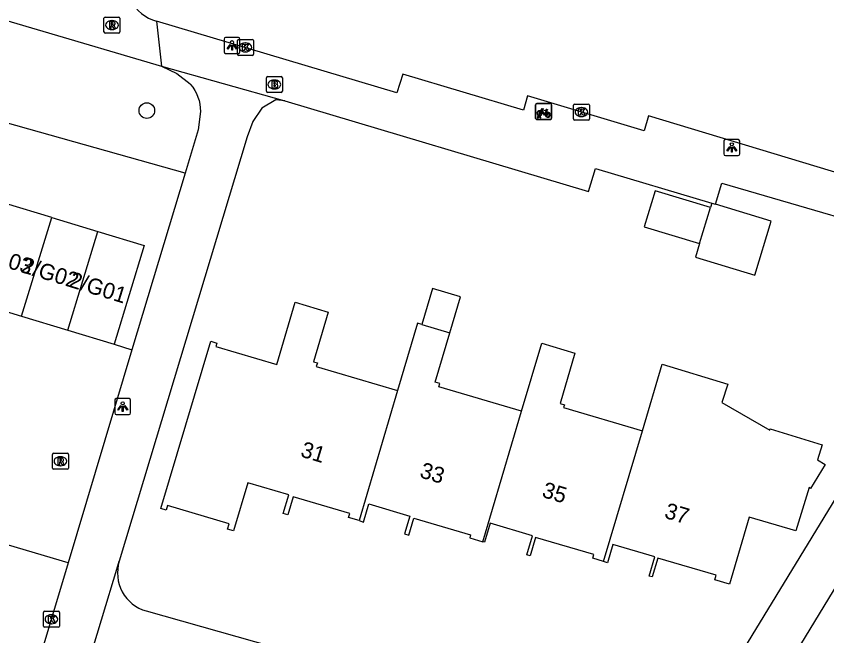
# Model space of a CAD drawing. Extents: x 162186 to 163152, y 385513 to 386513.
# Drawn here: x 162775.6 to 162826.3, y 386020.5 to 386059.3 of the extents above; entities that cross this region are included whole.
import ezdxf

# ---------------------------------------------------------------- set-up
doc = ezdxf.new("R2010")
doc.units = 0
for name, color, linetype in [('IMGEO_Boom', 7, 'Continuous'), ('IMGEO_Brandkraan', 7, 'Continuous'), ('IMGEO_Fietsenrek', 7, 'Continuous'), ('IMGEO_Groenvoorziening', 7, 'Continuous'), ('IMGEO_Kolk', 7, 'Continuous'), ('IMGEO_Lichtpunt', 7, 'Continuous'), ('IMGEO_Pand', 7, 'Continuous'), ('IMGEO_Pand_nummerreeks', 7, 'Continuous'), ('IMGEO_Rijbaan_lokaal_open', 7, 'Continuous'), ('IMGEO_Rioolput', 7, 'Continuous'), ('IMGEO_Voetpad_open', 7, 'Continuous')]:
    doc.layers.add(name, color=color, linetype=linetype)

msp = doc.modelspace()

# ---------------------------------------------------------------- linework, layer by layer
at = {"layer": 'IMGEO_Boom'}
msp.add_circle((162783.74, 386053.4), 0.489, dxfattribs=at)
at = {"layer": 'IMGEO_Brandkraan'}
for p, q in [((162791.228, 386054.612), (162791.228, 386055.464)), ((162791.303, 386055.538), (162792.155, 386055.538)), ((162792.229, 386055.464), (162792.229, 386054.612)), ((162791.716, 386055.318), (162791.741, 386055.318)), ((162792.155, 386054.538), (162791.303, 386054.538)), ((162791.739, 386054.758), (162791.714, 386054.758))]:
    msp.add_line(p, q, dxfattribs=at)
for points in [[(162791.228, 386054.612), (162791.228, 386055.464)], [(162791.303, 386055.538), (162792.155, 386055.538)], [(162792.229, 386055.464), (162792.229, 386054.612)], [(162791.576, 386055.238), (162791.576, 386054.838), (162791.789, 386054.838)], [(162791.807, 386055.238), (162791.576, 386055.238)], [(162791.755, 386055.157), (162791.701, 386055.157), (162791.701, 386055.081)], [(162791.701, 386055.081), (162791.754, 386055.081)], [(162791.763, 386055.005), (162791.701, 386055.005), (162791.701, 386054.924)], [(162791.701, 386054.924), (162791.763, 386054.924)], [(162792.155, 386054.538), (162791.303, 386054.538)]]:
    msp.add_lwpolyline(points, dxfattribs=at)
for centre, radius, start, end in [((162791.305, 386055.462), 0.0765, 91.552, 178.448), ((162791.305, 386055.462), 0.0765, 91.552, 178.448), ((162792.153, 386055.462), 0.0765, 1.552, 88.448), ((162792.153, 386055.462), 0.0765, 1.552, 88.448), ((162791.756, 386055.119), 0.0379, 267.8285, 90.9355), ((162791.764, 386054.964), 0.0404, 269.8759, 90.5077), ((162791.811, 386055.093), 0.145, 59.4692, 91.5367), ((162791.836, 386055.14), 0.0922, 285.5137, 58.1501), ((162791.841, 386054.948), 0.105, 301.3115, 78.989), ((162791.305, 386054.614), 0.0765, 181.552, 268.448), ((162791.305, 386054.614), 0.0765, 181.552, 268.448), ((162791.795, 386055.089), 0.251, 268.6676, 293.5347), ((162792.153, 386054.614), 0.0765, 271.552, 358.448), ((162792.153, 386054.614), 0.0765, 271.552, 358.448)]:
    msp.add_arc(centre, radius, start, end, dxfattribs=at)
for centre, major_axis, ratio, start_param, end_param in [((162791.715, 386055.038), (-0.387, 0.002), 0.722429, 4.712389, 7.853982), ((162791.74, 386055.038), (-0.39, 0.002), 0.717154, 1.570796, 4.712389)]:
    msp.add_ellipse(centre, major_axis=major_axis, ratio=ratio, start_param=start_param, end_param=end_param, dxfattribs=at)
at = {"layer": 'IMGEO_Fietsenrek'}
for p, q in [((162808.097, 386052.916), (162808.097, 386053.757)), ((162808.097, 386053.757), (162808.097, 386052.916)), ((162808.172, 386053.841), (162809.013, 386053.841)), ((162809.013, 386053.841), (162808.172, 386053.841)), ((162809.097, 386053.766), (162809.097, 386052.925)), ((162809.097, 386052.925), (162809.097, 386053.766)), ((162808.224, 386052.925), (162808.263, 386053.085)), ((162808.258, 386052.925), (162808.224, 386052.925)), ((162808.293, 386053.073), (162808.258, 386052.925)), ((162808.335, 386053.097), (162808.334, 386053.101)), ((162808.376, 386052.925), (162808.342, 386053.067)), ((162808.366, 386053.108), (162808.367, 386053.101)), ((162808.374, 386053.071), (162808.409, 386052.925)), ((162808.409, 386052.925), (162808.376, 386052.925)), ((162808.784, 386053.39), (162808.82, 386053.295)), ((162809.022, 386052.841), (162808.181, 386052.841)), ((162808.181, 386052.841), (162809.022, 386052.841))]:
    msp.add_line(p, q, dxfattribs=at)
for points in [[(162808.41, 386053.367), (162808.505, 386053.531), (162808.591, 386053.517), (162808.593, 386053.508), (162808.537, 386053.497), (162808.51, 386053.452), (162808.766, 386053.411)], [(162808.753, 386053.386), (162808.496, 386053.427), (162808.479, 386053.398), (162808.646, 386053.178), (162808.753, 386053.386)], [(162808.766, 386053.411), (162808.791, 386053.46), (162808.785, 386053.464), (162808.762, 386053.468), (162808.75, 386053.475), (162808.749, 386053.478), (162808.751, 386053.483), (162808.846, 386053.468), (162808.848, 386053.458), (162808.838, 386053.445), (162808.826, 386053.439), (162808.812, 386053.445), (162808.784, 386053.39)], [(162808.431, 386053.315), (162808.379, 386053.225), (162808.339, 386053.2), (162808.34, 386053.247), (162808.395, 386053.341)], [(162808.706, 386053.123), (162808.656, 386053.123), (162808.465, 386053.374), (162808.446, 386053.342)], [(162808.801, 386053.288), (162808.771, 386053.365), (162808.662, 386053.147), (162808.705, 386053.147)], [(162808.735, 386053.147), (162808.855, 386053.146), (162808.811, 386053.26)], [(162808.831, 386053.267), (162808.886, 386053.122), (162808.736, 386053.122)]]:
    msp.add_lwpolyline(points, dxfattribs=at)
for centre, radius, start, end in [((162808.175, 386053.763), 0.0779, 92.4484, 184.2845), ((162808.175, 386053.763), 0.0779, 92.4484, 184.2845), ((162809.019, 386053.763), 0.0779, 2.4484, 94.2845), ((162809.019, 386053.763), 0.0779, 2.4484, 94.2845), ((162808.175, 386052.919), 0.0779, 182.4484, 274.2845), ((162808.175, 386052.919), 0.0779, 182.4484, 274.2845), ((162808.337, 386053.226), 0.159, 62.6766, 242.1369), ((162808.337, 386053.226), 0.129, 63.3192, 238.903), ((162808.317, 386053.097), 0.0499, 12.8025, 158.6934), ((162808.337, 386053.226), 0.159, 253.9967, 271.7867), ((162808.317, 386053.097), 0.0174, 12.8025, 163.4502), ((162808.337, 386053.226), 0.129, 253.415, 269.0204), ((162808.337, 386053.226), 0.129, 283.6043, 43.4302), ((162808.337, 386053.226), 0.159, 283.5766, 46.6042), ((162808.864, 386053.142), 0.159, 113.3408, 178.3217), ((162808.864, 386053.142), 0.159, 187.0065, 105.7708), ((162808.864, 386053.142), 0.129, 113.923, 177.9556), ((162808.864, 386053.142), 0.129, 188.6715, 104.5883), ((162809.019, 386052.919), 0.0779, 272.4484, 4.2845), ((162809.019, 386052.919), 0.0779, 272.4484, 4.2845)]:
    msp.add_arc(centre, radius, start, end, dxfattribs=at)
at = {"layer": 'IMGEO_Groenvoorziening'}
msp.add_lwpolyline([(162786.142, 386049.469), (162754.435, 386058.403)], dxfattribs=at)
at = {"layer": 'IMGEO_Kolk'}
for p, q in [((162789.413, 386056.938), (162789.413, 386057.79)), ((162789.488, 386057.864), (162790.34, 386057.864)), ((162789.901, 386057.644), (162789.926, 386057.644)), ((162790.414, 386057.79), (162790.414, 386056.938)), ((162789.924, 386057.084), (162789.899, 386057.084)), ((162790.34, 386056.864), (162789.488, 386056.864)), ((162810.463, 386052.882), (162810.463, 386053.734)), ((162810.538, 386053.808), (162811.39, 386053.808)), ((162810.951, 386053.588), (162810.976, 386053.588)), ((162811.464, 386053.734), (162811.464, 386052.882)), ((162810.974, 386053.028), (162810.949, 386053.028)), ((162811.39, 386052.808), (162810.538, 386052.808)), ((162777.262, 386021.09), (162777.262, 386021.942)), ((162777.337, 386022.016), (162778.189, 386022.016)), ((162778.263, 386021.942), (162778.263, 386021.09)), ((162777.75, 386021.796), (162777.775, 386021.796)), ((162778.189, 386021.016), (162777.337, 386021.016)), ((162777.773, 386021.236), (162777.748, 386021.236))]:
    msp.add_line(p, q, dxfattribs=at)
for points in [[(162789.413, 386056.938), (162789.413, 386057.79)], [(162789.488, 386057.864), (162790.34, 386057.864)], [(162789.734, 386057.564), (162789.857, 386057.564), (162789.857, 386057.413), (162789.987, 386057.564), (162790.151, 386057.564), (162790.005, 386057.413), (162790.158, 386057.164), (162790.006, 386057.164), (162789.921, 386057.328), (162789.857, 386057.261), (162789.857, 386057.164), (162789.734, 386057.164), (162789.734, 386057.564)], [(162790.414, 386057.79), (162790.414, 386056.938)], [(162790.34, 386056.864), (162789.488, 386056.864)], [(162810.463, 386052.882), (162810.463, 386053.734)], [(162810.538, 386053.808), (162811.39, 386053.808)], [(162810.784, 386053.508), (162810.907, 386053.508), (162810.907, 386053.357), (162811.037, 386053.508), (162811.201, 386053.508), (162811.055, 386053.357), (162811.208, 386053.108), (162811.056, 386053.108), (162810.971, 386053.272), (162810.907, 386053.205), (162810.907, 386053.108), (162810.784, 386053.108), (162810.784, 386053.508)], [(162811.464, 386053.734), (162811.464, 386052.882)], [(162811.39, 386052.808), (162810.538, 386052.808)], [(162777.262, 386021.09), (162777.262, 386021.942)], [(162777.337, 386022.016), (162778.189, 386022.016)], [(162778.263, 386021.942), (162778.263, 386021.09)], [(162777.583, 386021.716), (162777.706, 386021.716), (162777.706, 386021.565), (162777.836, 386021.716), (162778, 386021.716), (162777.854, 386021.565), (162778.007, 386021.316), (162777.855, 386021.316), (162777.77, 386021.48), (162777.706, 386021.413), (162777.706, 386021.316), (162777.583, 386021.316), (162777.583, 386021.716)], [(162778.189, 386021.016), (162777.337, 386021.016)]]:
    msp.add_lwpolyline(points, dxfattribs=at)
for centre, start, end in [((162789.49, 386057.788), 91.552, 178.448), ((162789.49, 386057.788), 91.552, 178.448), ((162790.338, 386057.788), 1.552, 88.448), ((162790.338, 386057.788), 1.552, 88.448), ((162789.49, 386056.94), 181.552, 268.448), ((162789.49, 386056.94), 181.552, 268.448), ((162790.338, 386056.94), 271.552, 358.448), ((162790.338, 386056.94), 271.552, 358.448), ((162810.54, 386053.732), 91.552, 178.448), ((162810.54, 386053.732), 91.552, 178.448), ((162811.388, 386053.732), 1.552, 88.448), ((162811.388, 386053.732), 1.552, 88.448), ((162810.54, 386052.884), 181.552, 268.448), ((162810.54, 386052.884), 181.552, 268.448), ((162811.388, 386052.884), 271.552, 358.448), ((162811.388, 386052.884), 271.552, 358.448), ((162777.339, 386021.94), 91.552, 178.448), ((162777.339, 386021.94), 91.552, 178.448), ((162778.187, 386021.94), 1.552, 88.448), ((162778.187, 386021.94), 1.552, 88.448), ((162777.339, 386021.092), 181.552, 268.448), ((162777.339, 386021.092), 181.552, 268.448), ((162778.187, 386021.092), 271.552, 358.448), ((162778.187, 386021.092), 271.552, 358.448)]:
    msp.add_arc(centre, 0.0765, start, end, dxfattribs=at)
for centre, major_axis, ratio, start_param, end_param in [((162789.9, 386057.364), (-0.387, 0.002), 0.722429, 4.712389, 7.853982), ((162789.925, 386057.364), (-0.39, 0.002), 0.717154, 1.570796, 4.712389), ((162810.95, 386053.308), (-0.387, 0.002), 0.722429, 4.712389, 7.853982), ((162810.975, 386053.308), (-0.39, 0.002), 0.717154, 1.570796, 4.712389), ((162777.749, 386021.516), (-0.387, 0.002), 0.722429, 4.712389, 7.853982), ((162777.774, 386021.516), (-0.39, 0.002), 0.717154, 1.570796, 4.712389)]:
    msp.add_ellipse(centre, major_axis=major_axis, ratio=ratio, start_param=start_param, end_param=end_param, dxfattribs=at)
at = {"layer": 'IMGEO_Lichtpunt'}
for p, q in [((162789.482, 386057.983), (162788.674, 386057.983)), ((162789.482, 386057.983), (162788.674, 386057.983)), ((162788.58, 386057.888), (162788.58, 386057.081)), ((162788.58, 386057.888), (162788.58, 386057.081)), ((162789.576, 386057.081), (162789.576, 386057.888)), ((162789.576, 386057.081), (162789.576, 386057.888)), ((162788.674, 386056.987), (162789.482, 386056.987)), ((162788.674, 386056.987), (162789.482, 386056.987)), ((162819.888, 386051.491), (162819.888, 386050.684)), ((162819.888, 386051.491), (162819.888, 386050.684)), ((162820.79, 386051.586), (162819.982, 386051.586)), ((162820.79, 386051.586), (162819.982, 386051.586)), ((162820.884, 386050.684), (162820.884, 386051.491)), ((162820.884, 386050.684), (162820.884, 386051.491)), ((162819.982, 386050.59), (162820.79, 386050.59)), ((162819.982, 386050.59), (162820.79, 386050.59)), ((162781.729, 386035.252), (162781.729, 386034.445)), ((162781.729, 386035.252), (162781.729, 386034.445)), ((162782.631, 386035.347), (162781.823, 386035.347)), ((162782.631, 386035.347), (162781.823, 386035.347)), ((162782.725, 386034.445), (162782.725, 386035.252)), ((162782.725, 386034.445), (162782.725, 386035.252)), ((162781.823, 386034.351), (162782.631, 386034.351)), ((162781.823, 386034.351), (162782.631, 386034.351))]:
    msp.add_line(p, q, dxfattribs=at)
for points in [[(162788.954, 386057.552), (162788.993, 386057.524), (162788.805, 386057.262), (162788.767, 386057.289), (162788.954, 386057.552)], [(162789.056, 386057.504), (162789.103, 386057.504), (162789.103, 386057.182), (162789.056, 386057.182), (162789.056, 386057.504)], [(162789.166, 386057.524), (162789.204, 386057.551), (162789.391, 386057.289), (162789.352, 386057.261), (162789.166, 386057.524)], [(162820.262, 386051.155), (162820.301, 386051.127), (162820.113, 386050.865), (162820.075, 386050.892), (162820.262, 386051.155)], [(162820.364, 386051.107), (162820.411, 386051.107), (162820.411, 386050.785), (162820.364, 386050.785), (162820.364, 386051.107)], [(162820.474, 386051.127), (162820.512, 386051.154), (162820.699, 386050.892), (162820.66, 386050.864), (162820.474, 386051.127)], [(162782.103, 386034.916), (162782.142, 386034.888), (162781.954, 386034.626), (162781.916, 386034.653), (162782.103, 386034.916)], [(162782.205, 386034.868), (162782.252, 386034.868), (162782.252, 386034.546), (162782.205, 386034.546), (162782.205, 386034.868)], [(162782.315, 386034.888), (162782.353, 386034.915), (162782.54, 386034.653), (162782.501, 386034.625), (162782.315, 386034.888)]]:
    msp.add_lwpolyline(points, dxfattribs=at)
for centre in [(162789.079, 386057.686), (162820.387, 386051.289), (162782.228, 386035.05)]:
    msp.add_circle(centre, 0.0994, dxfattribs=at)
for centre, start, end in [((162788.674, 386057.888), 90, 180), ((162788.674, 386057.888), 90, 180), ((162789.482, 386057.888), 0, 90), ((162789.482, 386057.888), 0, 90), ((162788.674, 386057.081), 180, 270), ((162788.674, 386057.081), 180, 270), ((162789.482, 386057.081), 270, 0), ((162789.482, 386057.081), 270, 360), ((162819.982, 386051.491), 90, 180), ((162819.982, 386051.491), 90, 180), ((162820.79, 386051.491), 0, 90), ((162820.79, 386051.491), 0, 90), ((162819.982, 386050.684), 180, 270), ((162819.982, 386050.684), 180, 270), ((162820.79, 386050.684), 270, 0), ((162820.79, 386050.684), 270, 360), ((162781.823, 386035.252), 90, 180), ((162781.823, 386035.252), 90, 180), ((162782.631, 386035.252), 0, 90), ((162782.631, 386035.252), 0, 90), ((162781.823, 386034.445), 180, 270), ((162781.823, 386034.445), 180, 270), ((162782.631, 386034.445), 270, 0), ((162782.631, 386034.445), 270, 360)]:
    msp.add_arc(centre, 0.0946, start, end, dxfattribs=at)
at = {"layer": 'IMGEO_Pand'}
for points in [[(162819.052, 386047.327), (162815.584, 386048.378), (162814.898, 386046.116), (162818.366, 386045.064)], [(162777.78, 386046.707), (162774.884, 386047.587)], [(162818.366, 386045.064), (162818.11, 386044.222), (162821.837, 386043.092), (162822.861, 386046.466), (162819.359, 386047.527)], [(162818.366, 386045.064), (162819.052, 386047.327)], [(162819.133, 386047.596), (162819.052, 386047.327)], [(162819.133, 386047.596), (162819.359, 386047.527)], [(162775.898, 386040.51), (162777.78, 386046.707)], [(162777.78, 386046.707), (162780.676, 386045.828)], [(162778.794, 386039.631), (162780.676, 386045.828)], [(162780.676, 386045.828), (162783.572, 386044.948), (162781.69, 386038.751)], [(162802.727, 386039.464), (162803.396, 386041.719), (162801.632, 386042.242), (162800.963, 386039.987)], [(162773.002, 386041.39), (162775.898, 386040.51)], [(162797.032, 386027.695), (162796.376, 386027.89), (162796.452, 386028.147), (162792.915, 386029.196), (162792.577, 386028.057), (162792.284, 386028.144), (162792.632, 386029.317), (162790.076, 386030.076), (162789.178, 386027.05), (162788.797, 386027.163), (162788.894, 386027.491), (162785.032, 386028.637), (162784.949, 386028.355), (162784.626, 386028.451), (162787.741, 386038.948), (162788.134, 386038.831), (162788.072, 386038.623), (162791.879, 386037.493), (162793.033, 386041.382), (162795.107, 386040.767), (162794.185, 386037.662), (162794.423, 386037.592), (162794.357, 386037.368), (162799.448, 386035.858)], [(162775.898, 386040.51), (162778.794, 386039.631)], [(162800.963, 386039.987), (162800.697, 386040.066), (162799.448, 386035.858)], [(162800.963, 386039.987), (162802.727, 386039.464)], [(162778.794, 386039.631), (162781.69, 386038.751)], [(162807.21, 386034.551), (162802.024, 386036.09), (162802.085, 386036.294), (162801.811, 386036.375), (162802.727, 386039.464)], [(162807.21, 386034.551), (162808.48, 386038.823), (162810.562, 386038.205), (162809.624, 386035.046), (162809.901, 386034.964), (162809.85, 386034.793), (162814.791, 386033.327)], [(162814.791, 386033.327), (162816.029, 386037.497), (162820.145, 386036.249), (162819.765, 386035.108), (162822.771, 386033.363), (162822.797, 386033.449), (162826.049, 386032.458), (162825.758, 386031.503), (162826.226, 386031.22), (162825.322, 386029.703), (162825.237, 386029.781), (162824.401, 386027.065), (162821.479, 386027.917), (162820.233, 386023.717), (162819.318, 386023.989), (162819.401, 386024.269), (162815.749, 386025.353), (162815.396, 386024.164), (162815.208, 386024.22), (162815.566, 386025.425), (162812.943, 386026.204), (162812.603, 386025.058), (162812.353, 386025.132)], [(162799.448, 386035.858), (162797.032, 386027.695)], [(162804.782, 386026.377), (162807.21, 386034.551)], [(162812.353, 386025.132), (162814.791, 386033.327)], [(162797.032, 386027.695), (162797.317, 386027.611), (162797.653, 386028.743), (162800.22, 386027.98), (162799.892, 386026.872), (162800.153, 386026.794), (162800.469, 386027.86), (162804.021, 386026.806), (162803.966, 386026.619), (162804.782, 386026.377)], [(162812.353, 386025.132), (162811.671, 386025.334), (162811.74, 386025.564), (162808.091, 386026.647), (162807.748, 386025.491), (162807.551, 386025.55), (162807.905, 386026.743), (162805.256, 386027.529), (162804.903, 386026.341), (162804.782, 386026.377)]]:
    msp.add_lwpolyline(points, dxfattribs=at)
at = {"layer": 'IMGEO_Rijbaan_lokaal_open'}
for points in [[(162761.276, 386063.106), (162784.669, 386056.18)], [(162784.356, 386059.006), (162784.669, 386056.18)], [(162781.69, 386038.751), (162782.799, 386038.397)], [(162782.799, 386038.397), (162778.802, 386025.049)], [(162778.802, 386025.049), (162771.672, 386027.16)], [(162778.802, 386025.049), (162771.303, 386000), (162767.082, 385985.941)]]:
    msp.add_lwpolyline(points, dxfattribs=at)
msp.add_arc((162785.022, 386061.488), 2.57, 159.4855, 254.9781, dxfattribs=at)
at = {"layer": 'IMGEO_Rioolput'}
for p, q in [((162781.055, 386058.334), (162781.055, 386059.186)), ((162781.13, 386059.26), (162781.982, 386059.26)), ((162781.543, 386059.04), (162781.568, 386059.04)), ((162782.056, 386059.186), (162782.056, 386058.334)), ((162781.566, 386058.48), (162781.541, 386058.48)), ((162781.982, 386058.26), (162781.13, 386058.26)), ((162777.827, 386030.993), (162777.827, 386031.845)), ((162777.902, 386031.919), (162778.754, 386031.919)), ((162778.315, 386031.699), (162778.34, 386031.699)), ((162778.828, 386031.845), (162778.828, 386030.993)), ((162778.338, 386031.139), (162778.313, 386031.139)), ((162778.754, 386030.919), (162777.902, 386030.919))]:
    msp.add_line(p, q, dxfattribs=at)
for points in [[(162781.055, 386058.334), (162781.055, 386059.186)], [(162781.13, 386059.26), (162781.982, 386059.26)], [(162782.056, 386059.186), (162782.056, 386058.334)], [(162781.644, 386058.958), (162781.392, 386058.96), (162781.392, 386058.56)], [(162781.392, 386058.56), (162781.516, 386058.56), (162781.516, 386058.722), (162781.527, 386058.722)], [(162781.57, 386058.879), (162781.516, 386058.879), (162781.516, 386058.798)], [(162781.516, 386058.798), (162781.568, 386058.798)], [(162781.574, 386058.693), (162781.645, 386058.56), (162781.785, 386058.56), (162781.72, 386058.686)], [(162781.982, 386058.26), (162781.13, 386058.26)], [(162777.827, 386030.993), (162777.827, 386031.845)], [(162777.902, 386031.919), (162778.754, 386031.919)], [(162778.416, 386031.617), (162778.164, 386031.619), (162778.164, 386031.219)], [(162778.828, 386031.845), (162778.828, 386030.993)], [(162778.164, 386031.219), (162778.288, 386031.219), (162778.288, 386031.381), (162778.299, 386031.381)], [(162778.342, 386031.538), (162778.288, 386031.538), (162778.288, 386031.457)], [(162778.288, 386031.457), (162778.34, 386031.457)], [(162778.346, 386031.352), (162778.417, 386031.219), (162778.557, 386031.219), (162778.492, 386031.345)], [(162778.754, 386030.919), (162777.902, 386030.919)]]:
    msp.add_lwpolyline(points, dxfattribs=at)
for centre, radius, start, end in [((162781.132, 386059.184), 0.0765, 91.552, 178.448), ((162781.132, 386059.184), 0.0765, 91.552, 178.448), ((162781.98, 386059.184), 0.0765, 1.552, 88.448), ((162781.98, 386059.184), 0.0765, 1.552, 88.448), ((162781.526, 386058.669), 0.0533, 26.0293, 88.6989), ((162781.552, 386058.987), 0.19, 274.7715, 282.9687), ((162781.576, 386058.783), 0.0964, 77.0061, 93.1865), ((162781.59, 386058.84), 0.0378, 276.6634, 79.6772), ((162781.643, 386058.848), 0.109, 350.3612, 89.416), ((162781.641, 386058.848), 0.112, 277.5842, 350.9817), ((162781.625, 386058.633), 0.108, 29.5134, 73.7905), ((162781.132, 386058.336), 0.0765, 181.552, 268.448), ((162781.132, 386058.336), 0.0765, 181.552, 268.448), ((162781.98, 386058.336), 0.0765, 271.552, 358.448), ((162781.98, 386058.336), 0.0765, 271.552, 358.448), ((162777.904, 386031.843), 0.0765, 91.552, 178.448), ((162777.904, 386031.843), 0.0765, 91.552, 178.448), ((162778.415, 386031.507), 0.109, 350.3612, 89.416), ((162778.752, 386031.843), 0.0765, 1.552, 88.448), ((162778.752, 386031.843), 0.0765, 1.552, 88.448), ((162778.298, 386031.328), 0.0533, 26.0293, 88.6989), ((162778.324, 386031.646), 0.19, 274.7715, 282.9687), ((162778.348, 386031.442), 0.0964, 77.0061, 93.1865), ((162778.362, 386031.499), 0.0378, 276.6634, 79.6772), ((162778.413, 386031.507), 0.112, 277.5842, 350.9817), ((162778.397, 386031.292), 0.108, 29.5134, 73.7905), ((162777.904, 386030.995), 0.0765, 181.552, 268.448), ((162777.904, 386030.995), 0.0765, 181.552, 268.448), ((162778.752, 386030.995), 0.0765, 271.552, 358.448), ((162778.752, 386030.995), 0.0765, 271.552, 358.448)]:
    msp.add_arc(centre, radius, start, end, dxfattribs=at)
for centre, major_axis, ratio, start_param, end_param in [((162781.542, 386058.76), (-0.387, 0.002), 0.722429, 4.712389, 7.853982), ((162781.567, 386058.76), (-0.39, 0.002), 0.717154, 1.570796, 4.712389), ((162778.314, 386031.419), (-0.387, 0.002), 0.722429, 4.712389, 7.853982), ((162778.339, 386031.419), (-0.39, 0.002), 0.717154, 1.570796, 4.712389)]:
    msp.add_ellipse(centre, major_axis=major_axis, ratio=ratio, start_param=start_param, end_param=end_param, dxfattribs=at)
at = {"layer": 'IMGEO_Voetpad_open'}
for points in [[(162835.401, 386046.944), (162815.16, 386053.066), (162814.903, 386052.127), (162807.585, 386054.322), (162807.328, 386053.422), (162799.769, 386055.681), (162799.397, 386054.514), (162784.356, 386059.006)], [(162805.041, 385987.581), (162810.448, 385996.485), (162812.586, 386000), (162842.561, 386049.277), (162847.117, 386056.757)], [(162784.669, 386056.18), (162792.384, 386054.008)], [(162784.669, 386056.18), (162785.618, 386055.732), (162786.445, 386055.085), (162786.479, 386055.046), (162786.621, 386054.864), (162786.746, 386054.67), (162786.854, 386054.465), (162786.943, 386054.251), (162787.012, 386054.031), (162787.062, 386053.805), (162787.091, 386053.575), (162787.099, 386053.344), (162786.962, 386052.186), (162786.142, 386049.469)], [(162792.384, 386054.008), (162791.819, 386054.069), (162790.936, 386053.562), (162790.386, 386052.712), (162790.029, 386051.765), (162782.014, 386025.148)], [(162792.384, 386054.008), (162811.411, 386048.331), (162811.848, 386049.764), (162819.133, 386047.596)], [(162786.142, 386049.469), (162782.799, 386038.397)], [(162819.359, 386047.527), (162819.767, 386048.849), (162833.527, 386044.83)], [(162818.135, 386014.709), (162834.736, 386041.945)], [(162779.843, 386017.945), (162779.876, 386018.101), (162781.915, 386024.871), (162782.014, 386025.148)], [(162783.704, 386022.032), (162801.854, 386016.895), (162802.175, 386017.833), (162815.898, 386013.891)]]:
    msp.add_lwpolyline(points, dxfattribs=at)
msp.add_arc((162784.372, 386024.41), 2.47, 162.63, 254.3174, dxfattribs=at)

# ---------------------------------------------------------------- texts
at = {"layer": 'IMGEO_Pand_nummerreeks'}
for s, rotation, p in [('2/G03', 342.9526, (162772.92, 386044.173)), ('2/G02', 342.9526, (162775.804, 386043.289)), ('2/G01', 342.9526, (162778.806, 386042.368)), ('31', 343.1673, (162793.311, 386031.73)), ('33', 343.0806, (162800.78, 386030.426)), ('35', 343.1404, (162808.438, 386029.198)), ('37', 343.3203, (162816.104, 386027.887))]:
    msp.add_text(s, height=1, rotation=rotation, dxfattribs=at).set_placement(p)

doc.saveas('drawing.dxf')
